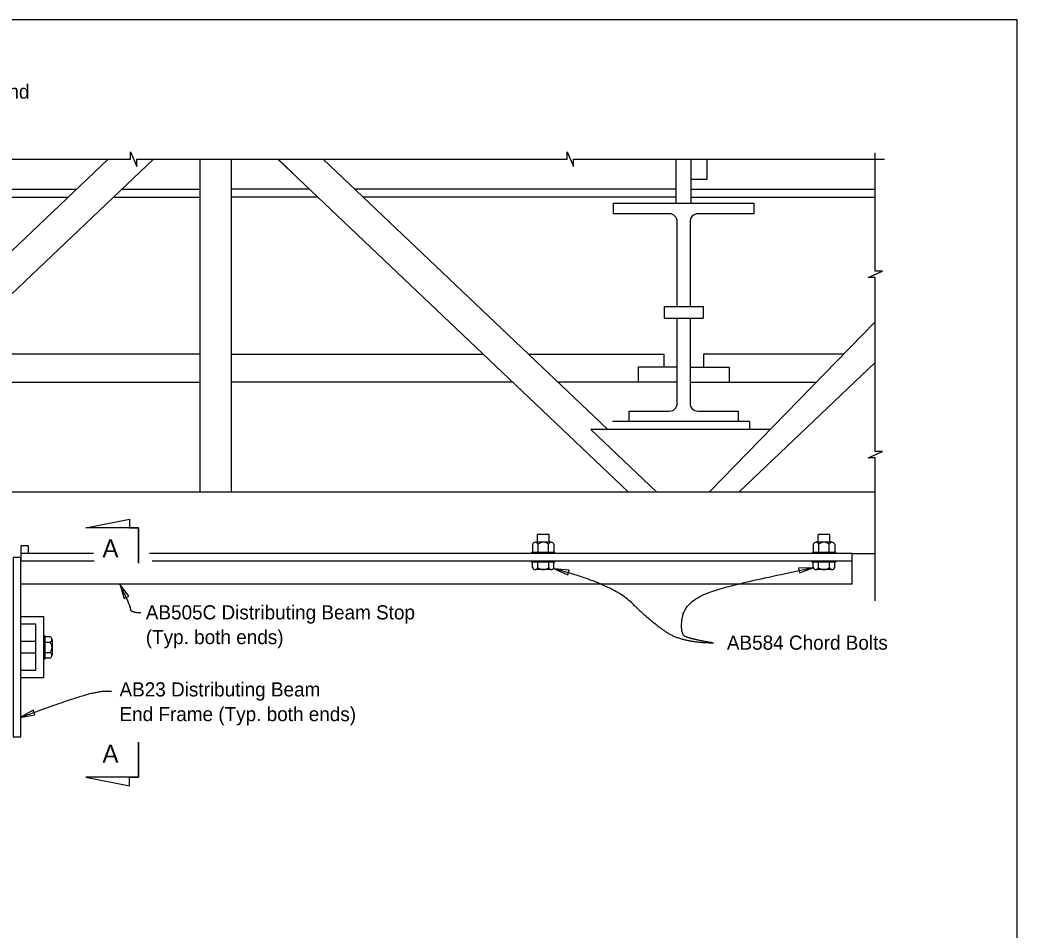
# Model space of a CAD drawing. Extents: x 112363.6 to 112390.2, y 109543.2 to 109558.
# Drawn here: x 112373.71 to 112379.04, y 109552.28 to 109557.15 of the extents above; entities that cross this region are included whole.
import ezdxf

# ---------------------------------------------------------------- set-up
doc = ezdxf.new("R2010")
doc.units = 0
for name, color, linetype in [('ActivePts-ConstElements', 7, 'Continuous'), ('Dimension', 7, 'Continuous'), ('SteelMisc', 7, 'Continuous'), ('SteelMisc_h', 7, 'Continuous'), ('Symbols', 7, 'Continuous'), ('TextStructures', 7, 'Continuous')]:
    doc.layers.add(name, color=color, linetype=linetype)

msp = doc.modelspace()

# ---------------------------------------------------------------- linework, layer by layer
at = {"layer": 'ActivePts-ConstElements'}
msp.add_lwpolyline([(112363.648, 109547.4173), (112379.0419, 109547.4173), (112379.0419, 109557.1471), (112363.648, 109557.1471)], close=True, dxfattribs=at)
at = {"layer": 'Dimension'}
for points in [[(112376.5688, 109554.2136), (112376.6409, 109554.1807), (112376.6477, 109554.2063)], [(112377.9532, 109554.2193), (112377.874, 109554.2168), (112377.8792, 109554.1909)], [(112374.2484, 109554.1303), (112374.2712, 109554.0544), (112374.2949, 109554.0662)], [(112373.7156, 109553.4183), (112373.7935, 109553.4325), (112373.7845, 109553.4574)]]:
    msp.add_lwpolyline(points, close=True, dxfattribs=at)
for points in [[(112377.4206, 109553.8164), (112377.2525, 109553.8164), (112377.0787, 109553.9348), (112376.8839, 109554.1296), (112376.5688, 109554.2136)], [(112377.4206, 109553.8164), (112377.2983, 109553.8374), (112377.241, 109553.8641), (112377.264, 109554.0303), (112377.4798, 109554.1239), (112377.9532, 109554.2193)], [(112374.3593, 109553.9778), (112374.3058, 109553.9778), (112374.3058, 109554.0144), (112374.2484, 109554.1303)], [(112374.2025, 109553.5574), (112374.1772, 109553.5574), (112374.1456, 109553.5574), (112374.0233, 109553.53), (112373.7156, 109553.4183)]]:
    msp.add_open_spline(points, degree=2, dxfattribs=at)
at = {"layer": 'SteelMisc'}
for p, q in [((112374.4278, 109556.4026), (112372.5568, 109554.6251)), ((112374.1858, 109556.4026), (112372.6656, 109554.9584)), ((112374.6769, 109554.6251), (112374.6769, 109556.4026)), ((112374.8436, 109554.6251), (112374.8436, 109556.4026)), ((112375.0927, 109556.4026), (112376.9637, 109554.6251)), ((112375.0933, 109556.4026), (112375.1753, 109556.3248)), ((112375.3347, 109556.4026), (112376.8549, 109554.9584)), ((112377.2198, 109556.1668), (112377.2198, 109556.4026)), ((112377.3007, 109556.1668), (112377.3007, 109556.4026)), ((112372.3007, 109556.242), (112374.0167, 109556.242)), ((112374.2588, 109556.242), (112374.677, 109556.242)), ((112375.1753, 109556.242), (112374.8436, 109556.242)), ((112375.2617, 109556.242), (112374.8436, 109556.242)), ((112377.2198, 109556.242), (112375.5038, 109556.242)), ((112377.3009, 109556.242), (112378.2843, 109556.242)), ((112372.3007, 109556.2003), (112373.9729, 109556.2003)), ((112374.2149, 109556.2003), (112374.677, 109556.2003)), ((112375.1753, 109556.2003), (112374.8436, 109556.2003)), ((112375.3056, 109556.2003), (112374.8436, 109556.2003)), ((112377.2198, 109556.2003), (112375.5476, 109556.2003)), ((112376.8854, 109556.1109), (112376.8854, 109556.1668)), ((112376.8854, 109556.1668), (112377.6353, 109556.1668)), ((112377.3009, 109556.2003), (112378.2843, 109556.2003)), ((112377.6353, 109556.1668), (112377.6353, 109556.1109)), ((112377.1845, 109556.1109), (112376.8854, 109556.1109)), ((112377.2262, 109555.6147), (112377.2262, 109556.0692)), ((112377.2945, 109556.0692), (112377.2945, 109555.6147)), ((112377.6353, 109556.1109), (112377.3362, 109556.1109)), ((112377.1562, 109555.6147), (112377.1562, 109555.5522)), ((112377.1562, 109555.6147), (112377.3645, 109555.6147)), ((112377.3645, 109555.6147), (112377.3645, 109555.5522)), ((112377.1562, 109555.5522), (112377.3645, 109555.5522)), ((112377.2262, 109555.0977), (112377.2262, 109555.5522)), ((112377.2945, 109555.5522), (112377.2945, 109555.0977)), ((112377.3982, 109554.6251), (112378.2843, 109555.5328)), ((112377.154, 109555.3609), (112377.154, 109555.2918)), ((112377.3667, 109555.3609), (112377.3667, 109555.2918)), ((112378.2843, 109555.316), (112377.557, 109554.6251)), ((112377.0179, 109555.2918), (112377.0179, 109555.2109)), ((112377.2262, 109555.2918), (112377.0179, 109555.2918)), ((112377.2945, 109555.2918), (112377.5028, 109555.2918)), ((112377.5028, 109555.2918), (112377.5028, 109555.2109)), ((112376.9687, 109555.0001), (112376.9687, 109555.056)), ((112376.9687, 109555.056), (112377.1845, 109555.056)), ((112377.3362, 109555.056), (112377.552, 109555.056)), ((112377.552, 109555.056), (112377.552, 109555.0001)), ((112377.612, 109555.0001), (112376.8794, 109555.0001)), ((112377.612, 109555.0001), (112377.612, 109554.9595)), ((112377.7235, 109554.9584), (112376.7642, 109554.9584)), ((112376.7642, 109554.9584), (112377.115, 109554.6251)), ((112363.8154, 109554.6251), (112378.2843, 109554.6251)), ((112376.5523, 109554.3553), (112376.4682, 109554.3553)), ((112376.4791, 109554.3553), (112376.4791, 109554.3975)), ((112376.5415, 109554.3975), (112376.4791, 109554.3975)), ((112376.5415, 109554.3553), (112376.5415, 109554.3975)), ((112378.0523, 109554.3553), (112377.9682, 109554.3553)), ((112377.9791, 109554.3553), (112377.9791, 109554.3975)), ((112378.0415, 109554.3975), (112377.9791, 109554.3975)), ((112378.0415, 109554.3553), (112378.0415, 109554.3975)), ((112376.4532, 109554.3448), (112376.4532, 109554.3004)), ((112376.4817, 109554.3448), (112376.4817, 109554.3004)), ((112376.5388, 109554.3004), (112376.5388, 109554.3448)), ((112376.5674, 109554.3448), (112376.5674, 109554.3004)), ((112377.9532, 109554.3448), (112377.9532, 109554.3004)), ((112377.9817, 109554.3448), (112377.9817, 109554.3004)), ((112378.0388, 109554.3004), (112378.0388, 109554.3448)), ((112378.0674, 109554.3448), (112378.0674, 109554.3004)), ((112374.1073, 109554.2944), (112373.7178, 109554.2944)), ((112378.1615, 109554.2944), (112374.4052, 109554.2944)), ((112376.4478, 109554.3004), (112376.4478, 109554.2947)), ((112376.5728, 109554.3004), (112376.4478, 109554.3004)), ((112376.5728, 109554.3004), (112376.5728, 109554.2947)), ((112377.9478, 109554.3004), (112377.9478, 109554.2947)), ((112378.0728, 109554.3004), (112377.9478, 109554.3004)), ((112378.0728, 109554.3004), (112378.0728, 109554.2947)), ((112378.1615, 109554.2944), (112378.2843, 109554.2944)), ((112378.1615, 109554.1304), (112378.1615, 109554.2944)), ((112378.1615, 109554.1304), (112373.7178, 109554.1304)), ((112373.7995, 109553.8245), (112373.7178, 109553.8245)), ((112373.846, 109553.8558), (112373.8403, 109553.8558)), ((112373.846, 109553.8558), (112373.846, 109553.7308)), ((112373.8746, 109553.8504), (112373.846, 109553.8504)), ((112373.8851, 109553.8353), (112373.8851, 109553.7512)), ((112373.846, 109553.8218), (112373.8746, 109553.8218)), ((112373.7995, 109553.7621), (112373.7178, 109553.7621)), ((112373.846, 109553.7308), (112373.8403, 109553.7308)), ((112373.8746, 109553.7647), (112373.846, 109553.7647)), ((112373.8746, 109553.7362), (112373.846, 109553.7362))]:
    msp.add_line(p, q, dxfattribs=at)
for points in [[(112377.384, 109556.4026), (112377.384, 109556.2947), (112377.3007, 109556.2947), (112377.3007, 109556.4026)], [(112374.6769, 109555.3609), (112373.3313, 109555.3609)], [(112374.8436, 109555.3609), (112375.1753, 109555.3609)], [(112374.8436, 109555.3609), (112376.1888, 109555.3609)], [(112376.4333, 109555.3609), (112377.154, 109555.3609)], [(112378.1164, 109555.3609), (112377.3667, 109555.3609)], [(112373.1734, 109555.2109), (112374.6769, 109555.2109)], [(112375.1753, 109555.2109), (112374.8436, 109555.2109)], [(112376.3501, 109555.2109), (112374.8436, 109555.2109)], [(112377.2262, 109555.2109), (112376.5924, 109555.2109)], [(112377.2945, 109555.2109), (112377.97, 109555.2109)], [(112377.552, 109555.0001), (112377.2605, 109555.0001), (112376.9687, 109555.0001)], [(112373.7587, 109554.2948), (112373.7587, 109554.3361), (112373.7178, 109554.3361), (112373.7178, 109554.2535)]]:
    msp.add_lwpolyline(points, dxfattribs=at)
for points in [[(112373.677, 109553.3153), (112373.7178, 109553.3153), (112373.7178, 109554.2737), (112373.677, 109554.2737)], [(112373.7178, 109553.9579), (112373.8403, 109553.9579), (112373.8403, 109553.6311), (112373.7178, 109553.6311), (112373.7178, 109553.672), (112373.7995, 109553.672), (112373.7995, 109553.917), (112373.7178, 109553.917)]]:
    msp.add_lwpolyline(points, close=True, dxfattribs=at)
for centre, radius, start, end in [((112377.1845, 109556.0692), 0.0417, 0, 90), ((112377.3362, 109556.0692), 0.0417, 90, 180), ((112377.1845, 109555.0977), 0.0417, 270, 0), ((112377.3362, 109555.0977), 0.0417, 180, 270), ((112376.4674, 109554.3403), 0.0149, 86.9846, 162.7442), ((112376.4674, 109554.3403), 0.0149, 17.2558, 86.9846), ((112376.5103, 109554.3112), 0.0441, 49.6401, 130.3599), ((112376.5531, 109554.3403), 0.0149, 93.0154, 162.7442), ((112376.5531, 109554.3403), 0.0149, 17.2558, 93.0154), ((112377.9674, 109554.3403), 0.0149, 86.9846, 162.7442), ((112377.9674, 109554.3403), 0.0149, 17.2558, 86.9846), ((112378.0103, 109554.3112), 0.0441, 49.6401, 130.3599), ((112378.0531, 109554.3403), 0.0149, 93.0154, 162.7442), ((112378.0531, 109554.3403), 0.0149, 17.2558, 93.0154), ((112373.8701, 109553.8361), 0.0149, 356.9846, 72.7442), ((112373.8701, 109553.8361), 0.0149, 287.2558, 356.9846), ((112373.841, 109553.7933), 0.0441, 319.6401, 40.3599), ((112373.8701, 109553.7504), 0.0149, 3.0154, 72.7442), ((112373.8701, 109553.7504), 0.0149, 287.2558, 3.0154)]:
    msp.add_arc(centre, radius, start, end, dxfattribs=at)
at = {"layer": 'SteelMisc_h'}
for p, q in [((112374.1108, 109554.2535), (112373.7178, 109554.2535)), ((112378.1615, 109554.2535), (112374.4196, 109554.2535)), ((112376.4478, 109554.2479), (112376.4478, 109554.2535)), ((112376.5728, 109554.2479), (112376.5728, 109554.2535)), ((112377.9478, 109554.2479), (112377.9478, 109554.2535)), ((112378.0728, 109554.2479), (112378.0728, 109554.2535)), ((112376.5728, 109554.2479), (112376.4478, 109554.2479)), ((112376.4532, 109554.2193), (112376.4532, 109554.2479)), ((112376.5523, 109554.2088), (112376.4682, 109554.2088)), ((112376.4817, 109554.2193), (112376.4817, 109554.2479)), ((112376.5388, 109554.2479), (112376.5388, 109554.2193)), ((112376.5674, 109554.2193), (112376.5674, 109554.2479)), ((112378.0728, 109554.2479), (112377.9478, 109554.2479)), ((112377.9532, 109554.2193), (112377.9532, 109554.2479)), ((112378.0523, 109554.2088), (112377.9682, 109554.2088)), ((112377.9817, 109554.2193), (112377.9817, 109554.2479)), ((112378.0388, 109554.2479), (112378.0388, 109554.2193)), ((112378.0674, 109554.2193), (112378.0674, 109554.2479))]:
    msp.add_line(p, q, dxfattribs=at)
for centre, radius, start, end in [((112376.4674, 109554.2238), 0.0149, 197.2558, 273.0154), ((112376.4674, 109554.2238), 0.0149, 273.0154, 342.7442), ((112376.5103, 109554.2529), 0.0441, 229.6401, 310.3599), ((112376.5531, 109554.2238), 0.0149, 197.2558, 266.9846), ((112376.5531, 109554.2238), 0.0149, 266.9846, 342.7442), ((112377.9674, 109554.2238), 0.0149, 197.2558, 273.0154), ((112377.9674, 109554.2238), 0.0149, 273.0154, 342.7442), ((112378.0103, 109554.2529), 0.0441, 229.6401, 310.3599), ((112378.0531, 109554.2238), 0.0149, 197.2558, 266.9846), ((112378.0531, 109554.2238), 0.0149, 266.9846, 342.7442)]:
    msp.add_arc(centre, radius, start, end, dxfattribs=at)
at = {"layer": 'Symbols'}
for points in [[(112372.6866, 109556.4026), (112374.3038, 109556.4026), (112374.3038, 109556.4413), (112374.3375, 109556.3638), (112374.3375, 109556.4026), (112375.2728, 109556.4026)], [(112374.6769, 109556.4026), (112376.6376, 109556.4026), (112376.6376, 109556.4413), (112376.6713, 109556.3638), (112376.6713, 109556.4026), (112378.3334, 109556.4026)], [(112378.2843, 109555.1861), (112378.2843, 109555.7697), (112378.2455, 109555.7697), (112378.323, 109555.8034), (112378.2843, 109555.8034), (112378.2843, 109556.4375)], [(112378.2843, 109554.0422), (112378.2843, 109554.8065), (112378.2455, 109554.8065), (112378.323, 109554.8402), (112378.2843, 109554.8402), (112378.2843, 109555.1861)]]:
    msp.add_lwpolyline(points, dxfattribs=at)
for points in [[(112374.3466, 109554.2439), (112374.3466, 109554.4314), (112374.0654, 109554.4314), (112374.2998, 109554.4783), (112374.2998, 109554.4314), (112374.3466, 109554.4314)], [(112374.3466, 109553.2868), (112374.3466, 109553.0993), (112374.0654, 109553.0993), (112374.2998, 109553.0524), (112374.2998, 109553.0993), (112374.3466, 109553.0993)]]:
    msp.add_lwpolyline(points, close=True, dxfattribs=at)

# ---------------------------------------------------------------- texts
at = {"layer": 'TextStructures'}
for s, height, p in [('Detour Bridge Superstructure (Truss and ', 0.0756, (112371.9384, 109556.7265)), ('A', 0.096, (112374.1547, 109554.2745)), ('AB505C Distributing Beam Stop', 0.0756, (112374.3863, 109553.9427)), ('(Typ. both ends)', 0.0756, (112374.3863, 109553.8107)), ('AB584 Chord Bolts', 0.0756, (112377.4914, 109553.7808)), ('AB23 Distributing Beam ', 0.0756, (112374.2457, 109553.5309)), ('End Frame (Typ. both ends)', 0.0756, (112374.2457, 109553.3989)), ('A', 0.096, (112374.1547, 109553.1768))]:
    msp.add_text(s, height=height, dxfattribs=at).set_placement(p)

doc.saveas('drawing.dxf')
